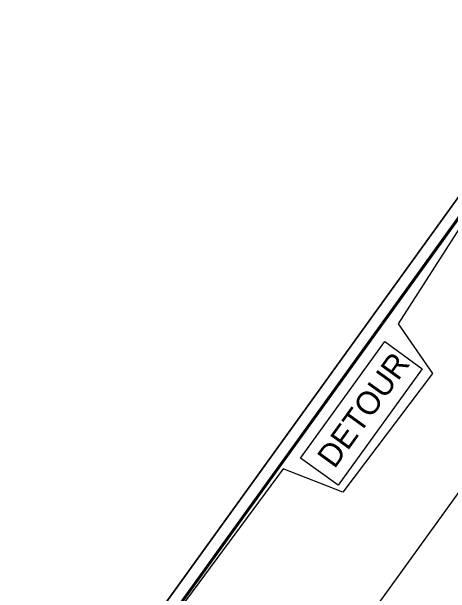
# Model space of a CAD drawing. Extents: x 2189185 to 2191058, y 386509 to 388561.
# Drawn here: x 2189185 to 2189944, y 387535 to 388541 of the extents above; entities that cross this region are included whole.
import ezdxf

# ---------------------------------------------------------------- set-up
doc = ezdxf.new("R2010")
doc.units = 0
for name, color, linetype in [('Prop Grid Mask', 7, 'Continuous'), ('Prop RDY Alternate Text Yellow', 7, 'Continuous'), ('Sheet Clip Boundary CELL', 7, 'Continuous'), ('Sheet Cutting Line CELL', 7, 'Continuous'), ('Sheet Layout Plan Border', 7, 'Continuous'), ('Sheet Plan CELL', 7, 'Continuous'), ('Sheet Plan Layout CELL', 7, 'Continuous'), ('Sheet Plot Border Inside CELL', 7, 'Continuous'), ('Sheet Plot Border Outside CELL', 7, 'Continuous')]:
    doc.layers.add(name, color=color, linetype=linetype)

msp = doc.modelspace()

# ---------------------------------------------------------------- linework, layer by layer
at = {"layer": 'Prop Grid Mask'}
msp.add_lwpolyline([(2189684.8, 387769), (2189830.2, 387970.6), (2189895.1, 387923.8), (2189749.7, 387722.2)], close=True, dxfattribs=at)
at = {"layer": 'Sheet Clip Boundary CELL'}
msp.add_lwpolyline([(2190166.8, 386710), (2190905.3, 387738.9), (2190256.9, 388232.8), (2190233.4, 388201.8), (2190061.1, 388326), (2189853.6, 388001.3), (2189912.6, 387915.4), (2189757.6, 387710.5), (2189654.6, 387750.5), (2189330.1, 387312.4)], close=True, dxfattribs=at)
at = {"layer": 'Sheet Cutting Line CELL'}
msp.add_line((2190169.9, 388515.4), (2189185.2, 387150), dxfattribs=at)
at = {"layer": 'Sheet Layout Plan Border'}
for points in [[(2190188.9, 387222.1), (2189805.8, 387498.4), (2190526.1, 388497.2), (2190654.9, 388404.3), (2190753.5, 388541.1), (2191007.8, 388357.7)], [(2190181.7, 386698.2), (2191000.6, 387833.8), (2190320.5, 388324.2), (2190209.8, 388170.7), (2190038.3, 388294.4), (2189330.1, 387312.4)]]:
    msp.add_lwpolyline(points, close=True, dxfattribs=at)
at = {"layer": 'Sheet Plan CELL'}
for points in [[(2190178.3, 388488.5), (2189300.8, 387271.9), (2190152.5, 386657.7), (2191029.9, 387874.3)], [(2190152.5, 386657.7), (2189300.8, 387271.8), (2190061.2, 388326.2), (2190182.9, 388238.5), (2190300, 388400.7), (2191029.9, 387874.3)]]:
    msp.add_lwpolyline(points, close=True, dxfattribs=at)
at = {"layer": 'Sheet Plan Layout CELL'}
msp.add_lwpolyline([(2189300.8, 387271.8), (2190152.5, 386657.7), (2191029.9, 387874.3), (2190349.8, 388364.8), (2190209.8, 388170.7), (2190038.3, 388294.4)], close=True, dxfattribs=at)
at = {"layer": 'Sheet Plot Border Inside CELL'}
msp.add_lwpolyline([(2190064.7, 386531.7), (2191039.2, 387883), (2190183.5, 388500.1), (2189209, 387148.8)], close=True, dxfattribs=at)
at = {"layer": 'Sheet Plot Border Outside CELL'}
msp.add_lwpolyline([(2190073.3, 386509.5), (2191058.1, 387874.9), (2190169.9, 388515.4), (2189185.2, 387150)], close=True, dxfattribs=at)

# ---------------------------------------------------------------- texts
at = {"layer": 'Prop RDY Alternate Text Yellow'}
msp.add_text('DETOUR', height=40, rotation=54.2018, dxfattribs=at).set_placement((2189743.3, 387749.5))

doc.saveas('drawing.dxf')
